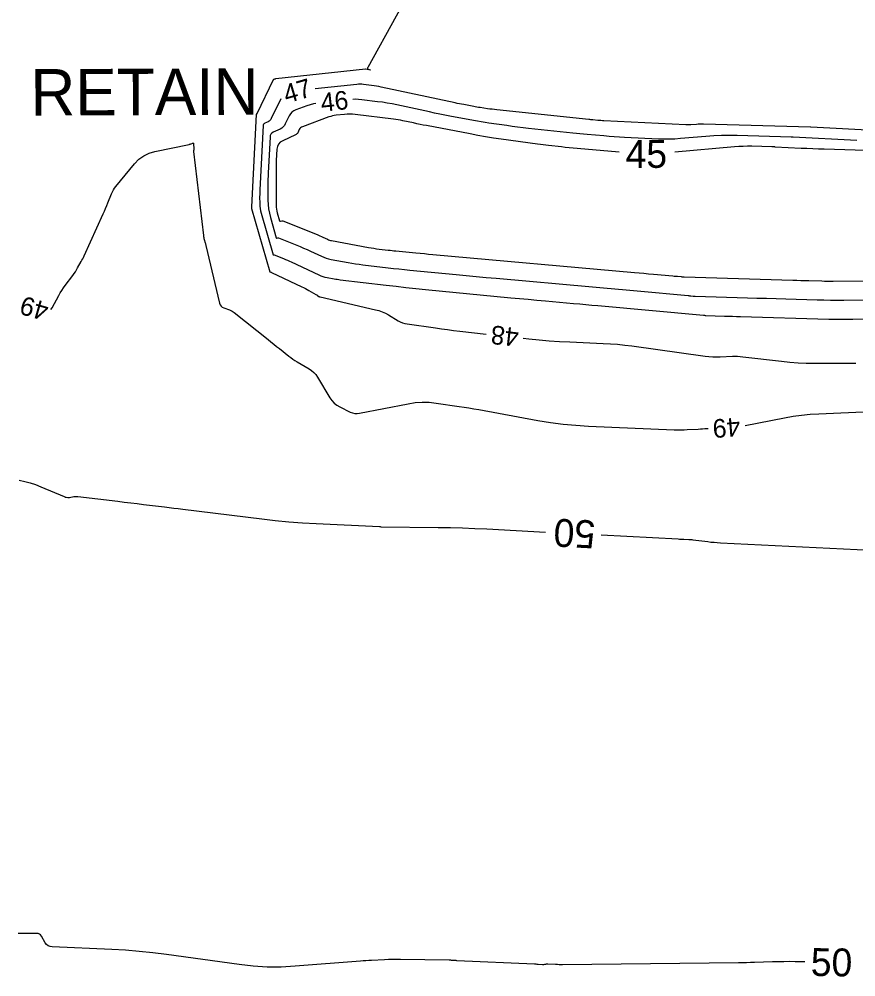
# Model space of a CAD drawing. Extents: x 2384780 to 2405861, y 547869 to 573706.
# Drawn here: x 2393194.6 to 2393284.5, y 552620 to 552723.1 of the extents above; entities that cross this region are included whole.
import ezdxf

# ---------------------------------------------------------------- set-up
doc = ezdxf.new("R2010")
doc.units = 0
for name, color, linetype in [('Breaklines', 7, 'Continuous'), ('Old_Level_60', 7, 'Continuous'), ('Old_Level_61', 7, 'Continuous')]:
    doc.layers.add(name, color=color, linetype=linetype)

msp = doc.modelspace()

# ---------------------------------------------------------------- linework, layer by layer
at = {"layer": 'Old_Level_60'}
for points in [[(2393238.1735, 552728.95825), (2393232.05975, 552717.871), (2393232.03925, 552717.81675), (2393232.0415, 552717.76975), (2393232.06625, 552717.7295), (2393232.11375, 552717.6965), (2393232.30575, 552717.59975), (2393232.33625, 552717.583), (2393232.345, 552717.5735), (2393232.33225, 552717.572), (2393232.298, 552717.57775), (2393231.8365, 552717.677), (2393231.833, 552717.67775), (2393231.82925, 552717.67825), (2393231.82575, 552717.67875), (2393231.822, 552717.67925), (2393231.81, 552717.68075), (2393231.8075, 552717.681), (2393231.80475, 552717.68125), (2393231.80225, 552717.681), (2393231.79975, 552717.681), (2393222.153, 552716.63275), (2393222.1245, 552716.62875), (2393222.09625, 552716.623), (2393222.06875, 552716.61575), (2393222.0415, 552716.60675), (2393221.953, 552716.57425), (2393221.93525, 552716.566), (2393221.92, 552716.55475), (2393221.9075, 552716.541), (2393221.8975, 552716.524), (2393220.1425, 552712.8735), (2393220.13625, 552712.863), (2393220.12875, 552712.854), (2393220.1195, 552712.8465), (2393220.109, 552712.8405), (2393220.07175, 552712.82325), (2393220.06475, 552712.819), (2393220.0595, 552712.8135), (2393220.05625, 552712.80675), (2393220.055, 552712.7985), (2393219.549, 552702.88225), (2393219.54825, 552702.86175), (2393219.5475, 552702.84125), (2393219.54725, 552702.82075), (2393219.54725, 552702.8), (2393219.5475, 552702.733), (2393219.548, 552702.7185), (2393219.5495, 552702.7045), (2393219.552, 552702.69025), (2393219.5555, 552702.6765), (2393221.52225, 552695.88275), (2393221.52275, 552695.88175), (2393221.5235, 552695.881), (2393221.5245, 552695.88075), (2393221.52575, 552695.88075), (2393221.53025, 552695.882), (2393221.53125, 552695.88225), (2393221.532, 552695.88225), (2393221.533, 552695.882), (2393221.534, 552695.88175), (2393221.62725, 552695.8445), (2393221.647, 552695.8365), (2393221.66675, 552695.828), (2393221.6865, 552695.81925), (2393221.706, 552695.81025), (2393224.972, 552694.274), (2393225.16225, 552694.18225), (2393225.35025, 552694.0865), (2393225.53625, 552693.987), (2393225.72025, 552693.8835), (2393226.48175, 552693.44475), (2393226.5275, 552693.4175), (2393226.5725, 552693.38925), (2393226.617, 552693.36), (2393226.66075, 552693.3295), (2393226.80225, 552693.2285), (2393226.83325, 552693.2085), (2393226.866, 552693.19175), (2393226.9, 552693.1785), (2393226.9355, 552693.1685)], [(2393294.628, 552710.66525), (2393279.71925, 552711.4425), (2393279.715, 552711.44275), (2393279.7105, 552711.443), (2393279.706, 552711.44325), (2393279.7015, 552711.44325), (2393279.687, 552711.44375), (2393279.684, 552711.44375), (2393279.681, 552711.444), (2393279.67775, 552711.444), (2393279.67475, 552711.44425), (2393268.15125, 552711.7675), (2393267.964, 552711.77), (2393267.77675, 552711.76725), (2393267.59, 552711.759), (2393267.40325, 552711.74525), (2393266.79325, 552711.69175), (2393266.6625, 552711.6825), (2393266.53175, 552711.67775), (2393266.40075, 552711.67775), (2393266.26975, 552711.682), (2393257.4505, 552712.1285), (2393257.28775, 552712.1375), (2393257.125, 552712.14825), (2393256.9625, 552712.16025), (2393256.8, 552712.174), (2393256.26925, 552712.2215), (2393256.15575, 552712.232), (2393256.042, 552712.24275), (2393255.9285, 552712.254), (2393255.815, 552712.26575), (2393245.93525, 552713.3075), (2393245.687, 552713.33475), (2393245.439, 552713.36425), (2393245.19125, 552713.39575), (2393244.94375, 552713.42925), (2393244.13575, 552713.54275), (2393243.96275, 552713.568), (2393243.79025, 552713.5955), (2393243.618, 552713.62525), (2393243.44625, 552713.65725), (2393242.37275, 552713.8635), (2393242.143, 552713.90825), (2393241.91325, 552713.9545), (2393241.684, 552714.00175), (2393241.45475, 552714.05025), (2393233.50675, 552715.7575), (2393233.2485, 552715.81), (2393232.9895, 552715.8565), (2393232.72925, 552715.89725), (2393232.46825, 552715.932), (2393231.614, 552716.0365), (2393231.43075, 552716.0535), (2393231.2475, 552716.06), (2393231.06425, 552716.056), (2393230.881, 552716.04125), (2393226.408, 552715.55525)], [(2393222.70025, 552714.48025), (2393221.6805, 552712.3595), (2393221.6185, 552712.25375), (2393221.54175, 552712.163), (2393221.44975, 552712.08775), (2393221.343, 552712.02775), (2393220.96975, 552711.85625), (2393220.89925, 552711.813), (2393220.8475, 552711.757), (2393220.81475, 552711.68825), (2393220.80075, 552711.60675), (2393220.448, 552704.6885), (2393220.44025, 552704.51375), (2393220.43475, 552704.33925), (2393220.432, 552704.1645), (2393220.43125, 552703.98975)], [(2393226.48025, 552714.00275), (2393226.21275, 552713.94875), (2393225.85, 552713.8525), (2393225.4925, 552713.734), (2393224.333, 552713.31075), (2393224.10125, 552713.2015), (2393223.90275, 552713.0555), (2393223.738, 552712.8725), (2393223.60675, 552712.6525), (2393223.19, 552711.786), (2393223.0885, 552711.61275), (2393222.9625, 552711.46425), (2393222.812, 552711.341), (2393222.637, 552711.2425), (2393221.88575, 552710.89725), (2393221.74375, 552710.8105), (2393221.63975, 552710.69775), (2393221.57375, 552710.5595), (2393221.54575, 552710.39525), (2393221.34725, 552706.507), (2393221.3325, 552706.17225), (2393221.32225, 552705.83725), (2393221.31675, 552705.50225), (2393221.3155, 552705.16725)], [(2393284.63775, 552710.01775), (2393277.792, 552710.37475), (2393277.7725, 552710.37575), (2393277.75275, 552710.3765), (2393277.73325, 552710.37725), (2393277.71375, 552710.378), (2393277.65, 552710.38), (2393277.63625, 552710.3805), (2393277.6225, 552710.38075), (2393277.60875, 552710.38125), (2393277.59525, 552710.3815), (2393271.7785, 552710.54475), (2393270.9375, 552710.55625), (2393270.0975, 552710.5435), (2393269.258, 552710.50625), (2393268.41925, 552710.445), (2393265.68075, 552710.20475), (2393265.09375, 552710.16325), (2393264.50625, 552710.14225), (2393263.9185, 552710.14175), (2393263.3305, 552710.16125), (2393259.66625, 552710.34675), (2393259.113, 552710.3775), (2393258.56025, 552710.4135), (2393258.00775, 552710.45475), (2393257.4555, 552710.5015), (2393255.65275, 552710.663), (2393255.2665, 552710.69825), (2393254.88025, 552710.73525), (2393254.49425, 552710.7735), (2393254.1085, 552710.8135), (2393249.35675, 552711.3145), (2393248.76675, 552711.37925), (2393248.177, 552711.44925), (2393247.58825, 552711.524), (2393246.99975, 552711.604), (2393245.079, 552711.8735), (2393244.66775, 552711.93375), (2393244.2575, 552711.99925), (2393243.848, 552712.07), (2393243.4395, 552712.14575), (2393240.88775, 552712.63625), (2393240.34125, 552712.74275), (2393239.79525, 552712.85225), (2393239.25, 552712.96475), (2393238.70525, 552713.08025), (2393235.17675, 552713.83825), (2393234.66425, 552713.94225), (2393234.14975, 552714.03475), (2393233.633, 552714.1155), (2393233.11475, 552714.18475), (2393231.41775, 552714.392), (2393231.054, 552714.426), (2393230.69025, 552714.43875), (2393230.45575, 552714.43375)], [(2393197.9695, 552691.81775), (2393198.10475, 552692), (2393198.82275, 552693.32125), (2393198.9815, 552693.60125), (2393199.1505, 552693.87475), (2393199.32925, 552694.14175), (2393199.51825, 552694.40225), (2393200.333, 552695.4845), (2393200.47475, 552695.6795), (2393200.60925, 552695.879), (2393200.73675, 552696.08325), (2393200.85725, 552696.292), (2393201.23925, 552696.981), (2393201.31975, 552697.1295), (2393201.39725, 552697.2795), (2393201.47175, 552697.43075), (2393201.54325, 552697.58375), (2393203.60525, 552702.1035), (2393203.73825, 552702.4), (2393203.86775, 552702.698), (2393203.99375, 552702.99775), (2393204.11575, 552703.299), (2393204.50925, 552704.28525), (2393204.601, 552704.49225), (2393204.708, 552704.69025), (2393204.83, 552704.87925), (2393204.967, 552705.0595), (2393206.97925, 552707.506), (2393207.43975, 552707.98175), (2393207.9585, 552708.36075), (2393208.53575, 552708.64275), (2393209.1715, 552708.828), (2393212.84625, 552709.5835), (2393212.9025, 552709.59675), (2393212.9575, 552709.613), (2393213.0115, 552709.63225), (2393213.0645, 552709.65475), (2393213.236, 552709.733), (2393213.2685, 552709.7425), (2393213.292, 552709.738), (2393213.30675, 552709.719), (2393213.31275, 552709.68575), (2393213.33575, 552709.0925), (2393213.33625, 552709.06625), (2393213.3365, 552709.04), (2393213.33575, 552709.0135), (2393213.33425, 552708.98725), (2393213.32875, 552708.90125), (2393213.328, 552708.883), (2393213.32825, 552708.8645), (2393213.329, 552708.84625), (2393213.33075, 552708.82775), (2393214.38525, 552699.7715), (2393214.40025, 552699.6645), (2393214.41975, 552699.5585), (2393214.444, 552699.45325), (2393214.47275, 552699.34925), (2393214.5745, 552699.0105), (2393214.59575, 552698.93775), (2393214.616, 552698.86475), (2393214.635, 552698.7915), (2393214.653, 552698.71775), (2393216.11275, 552692.519), (2393216.17675, 552692.33925), (2393216.27675, 552692.19175), (2393216.4125, 552692.07625), (2393216.5845, 552691.99325), (2393217.20425, 552691.77425), (2393217.33425, 552691.72225), (2393217.4585, 552691.66), (2393217.577, 552691.5875), (2393217.69, 552691.50475), (2393221.3405, 552688.591), (2393221.64675, 552688.34625), (2393221.95275, 552688.10125), (2393222.2585, 552687.85575), (2393222.56375, 552687.61), (2393223.561, 552686.8065), (2393223.7775, 552686.6385), (2393224, 552686.479), (2393224.228, 552686.3275), (2393224.46175, 552686.1845), (2393225.75125, 552685.42725), (2393226.01375, 552685.25075), (2393226.2485, 552685.0465), (2393226.45575, 552684.81425), (2393226.635, 552684.55375), (2393227.9805, 552682.324), (2393228.1955, 552682.01725), (2393228.447, 552681.7505), (2393228.735, 552681.52325), (2393229.05925, 552681.33575), (2393230.178, 552680.7885), (2393230.4205, 552680.69225), (2393230.6685, 552680.63825), (2393230.922, 552680.6265), (2393231.181, 552680.657), (2393236.38975, 552681.6815), (2393237.1415, 552681.797), (2393237.895, 552681.8485), (2393238.65, 552681.8355)], [(2393221.3155, 552705.16725), (2393221.32125, 552703.603), (2393221.3395, 552703.1265), (2393221.3905, 552702.655), (2393221.47425, 552702.188), (2393221.591, 552701.7255), (2393222.22225, 552699.545), (2393222.23275, 552699.52175), (2393222.24825, 552699.50725), (2393222.2685, 552699.50175), (2393222.29375, 552699.50475), (2393222.38475, 552699.5295), (2393222.404, 552699.533), (2393222.42325, 552699.5335), (2393222.44225, 552699.531), (2393222.461, 552699.525), (2393224.427, 552698.73875), (2393224.7955, 552698.58825), (2393225.1615, 552698.43225), (2393225.52525, 552698.271), (2393225.88675, 552698.10425), (2393227.06375, 552697.55075), (2393227.3185, 552697.44075), (2393227.579, 552697.3475), (2393227.845, 552697.27175), (2393228.11625, 552697.21275), (2393229.9535, 552696.8755), (2393230.34775, 552696.8065), (2393230.74275, 552696.74375), (2393231.139, 552696.68725), (2393231.536, 552696.63725), (2393234.248, 552696.31825), (2393234.82925, 552696.25125), (2393235.41075, 552696.18725), (2393235.99275, 552696.126), (2393236.575, 552696.06775), (2393241.57575, 552695.58), (2393242.6475, 552695.4765), (2393243.7195, 552695.37525), (2393244.7915, 552695.276), (2393245.86375, 552695.17925), (2393256.21775, 552694.25475), (2393257.4235, 552694.147), (2393258.629, 552694.0385), (2393259.8345, 552693.92925), (2393261.04, 552693.81975), (2393266.518, 552693.32025), (2393266.59175, 552693.3135), (2393266.6655, 552693.307), (2393266.73925, 552693.30025), (2393266.813, 552693.29375), (2393267.05375, 552693.27225), (2393267.10525, 552693.268), (2393267.157, 552693.2645), (2393267.20875, 552693.26175), (2393267.2605, 552693.25975), (2393272.8845, 552693.08825), (2393273.915, 552693.057), (2393274.94575, 552693.026), (2393275.97625, 552692.99525), (2393277.007, 552692.96475), (2393280.37375, 552692.866), (2393281.095, 552692.848), (2393281.81675, 552692.836), (2393282.53825, 552692.83025), (2393283.26, 552692.83075), (2393287.00075, 552692.84875)], [(2393220.43125, 552703.98975), (2393220.43425, 552703.17425), (2393220.44375, 552702.92575), (2393220.47025, 552702.67975), (2393220.514, 552702.43625), (2393220.575, 552702.195), (2393221.87225, 552697.714), (2393221.87775, 552697.70175), (2393221.88575, 552697.69425), (2393221.8965, 552697.69125), (2393221.90975, 552697.69275), (2393221.9575, 552697.70575), (2393221.96775, 552697.70775), (2393221.97775, 552697.708), (2393221.98775, 552697.7065), (2393221.9975, 552697.7035), (2393222.991, 552697.306), (2393223.20325, 552697.2195), (2393223.414, 552697.12975), (2393223.6235, 552697.03675), (2393223.8315, 552696.94075), (2393226.78675, 552695.55075), (2393227.0035, 552695.45725), (2393227.22475, 552695.378), (2393227.45075, 552695.3135), (2393227.6815, 552695.2635), (2393228.44275, 552695.12375), (2393228.606, 552695.09525), (2393228.76975, 552695.06925), (2393228.93375, 552695.04575), (2393229.09825, 552695.025), (2393234.0375, 552694.444), (2393235.096, 552694.322), (2393236.15525, 552694.2055), (2393237.215, 552694.094), (2393238.2755, 552693.988), (2393247.4365, 552693.094), (2393248.36625, 552693.00425), (2393249.296, 552692.9165), (2393250.22625, 552692.8305), (2393251.1565, 552692.7465), (2393254.1955, 552692.47525), (2393254.84675, 552692.41675), (2393255.498, 552692.35825), (2393256.149, 552692.29925), (2393256.80025, 552692.24), (2393268.154, 552691.205), (2393268.18125, 552691.2025), (2393268.2085, 552691.2), (2393268.236, 552691.1975), (2393268.26325, 552691.195), (2393268.3525, 552691.187), (2393268.3715, 552691.1855), (2393268.39075, 552691.18425), (2393268.40975, 552691.18325), (2393268.429, 552691.1825), (2393270.422, 552691.12175), (2393270.84925, 552691.10875), (2393271.27625, 552691.096), (2393271.70325, 552691.08325), (2393272.1305, 552691.0705), (2393281.6255, 552690.792), (2393281.8845, 552690.7855), (2393282.1435, 552690.78125), (2393282.40275, 552690.77925), (2393282.662, 552690.77925), (2393283.5085, 552690.7835), (2393283.69, 552690.78475), (2393283.8715, 552690.78675), (2393284.05275, 552690.7895), (2393284.23425, 552690.793), (2393297.52775, 552691.08425)], [(2393226.9355, 552693.1685), (2393232.89875, 552691.795), (2393233.25875, 552691.6975), (2393233.60775, 552691.573), (2393233.94625, 552691.4215), (2393234.27375, 552691.243), (2393235.32575, 552690.616), (2393235.5555, 552690.49375), (2393235.794, 552690.39575), (2393236.04075, 552690.322), (2393236.29625, 552690.2725), (2393239.33325, 552689.8345), (2393239.98425, 552689.74325), (2393240.636, 552689.65725), (2393241.2885, 552689.57675), (2393241.9415, 552689.5015), (2393244.789, 552689.1845)], [(2393248.7645, 552688.74225), (2393249.38075, 552688.67375), (2393250.47925, 552688.561), (2393251.579, 552688.46675), (2393252.68, 552688.391), (2393253.78275, 552688.334), (2393257.387, 552688.178), (2393258.1585, 552688.1355), (2393258.92825, 552688.07525), (2393259.6965, 552687.99675), (2393260.46325, 552687.9005), (2393268.35325, 552686.81575), (2393268.753, 552686.76975), (2393269.1535, 552686.7415), (2393269.555, 552686.73075), (2393269.95725, 552686.73775), (2393271.2725, 552686.78975), (2393271.55425, 552686.79525), (2393271.8355, 552686.7895), (2393272.11625, 552686.77275), (2393272.3965, 552686.74475), (2393276.54575, 552686.247), (2393277.4355, 552686.15375), (2393278.327, 552686.087), (2393279.22025, 552686.047), (2393280.115, 552686.0335), (2393283.2175, 552686.03325), (2393283.8825, 552686.03675), (2393284.547, 552686.04725)], [(2393238.65, 552681.8355), (2393239.40675, 552681.7585), (2393241.8815, 552681.4015), (2393242.41125, 552681.3225), (2393242.94025, 552681.2385), (2393243.4685, 552681.1495), (2393243.996, 552681.0555), (2393250.3355, 552679.8935), (2393251.69675, 552679.668), (2393253.06325, 552679.49), (2393254.435, 552679.35925), (2393255.81225, 552679.276), (2393265.005, 552678.878), (2393265.359, 552678.86725), (2393265.71275, 552678.86575), (2393266.0665, 552678.8735), (2393266.42025, 552678.89075), (2393267.57525, 552678.96175), (2393267.823, 552678.97625), (2393268.0705, 552678.9895), (2393268.31825, 552679.00125), (2393268.566, 552679.012), (2393268.648, 552679.01525)], [(2393272.631, 552679.32575), (2393276.86925, 552680.1665), (2393277.78825, 552680.3305), (2393278.71175, 552680.459), (2393279.63925, 552680.55175), (2393280.57125, 552680.609), (2393286.1155, 552680.8425)]]:
    msp.add_lwpolyline(points, dxfattribs=at)
at = {"layer": 'Old_Level_61'}
for points in [[(2393259.08675, 552708.74175), (2393254.56075, 552709.147), (2393254.1395, 552709.1855), (2393253.71825, 552709.22575), (2393253.2975, 552709.2675), (2393252.8765, 552709.311), (2393251.50225, 552709.456), (2393251.208, 552709.48825), (2393250.914, 552709.52325), (2393250.62025, 552709.5605), (2393250.32675, 552709.6005), (2393246.4035, 552710.15075), (2393245.56375, 552710.274), (2393244.72575, 552710.40775), (2393243.88925, 552710.55225), (2393243.05475, 552710.707), (2393238.3865, 552711.60425), (2393238.031, 552711.6735), (2393237.67625, 552711.74475), (2393237.3215, 552711.818), (2393236.9675, 552711.893), (2393235.81125, 552712.14125), (2393235.563, 552712.19175), (2393235.31375, 552712.2365), (2393235.0635, 552712.27575), (2393234.8125, 552712.30925), (2393230.696, 552712.81175), (2393230.4145, 552712.838), (2393230.13325, 552712.848), (2393229.85175, 552712.84175), (2393229.57025, 552712.81925), (2393228.65025, 552712.71925), (2393228.45425, 552712.692), (2393228.26125, 552712.65325), (2393228.071, 552712.60275), (2393227.88325, 552712.5405), (2393225.02075, 552711.4955), (2393224.91625, 552711.44625), (2393224.82675, 552711.38025), (2393224.75225, 552711.29775), (2393224.693, 552711.1985), (2393224.524, 552710.847), (2393224.48275, 552710.77675), (2393224.43175, 552710.7165), (2393224.37075, 552710.6665), (2393224.29975, 552710.6265), (2393222.91225, 552709.989), (2393222.65, 552709.82875), (2393222.458, 552709.62075), (2393222.336, 552709.36525), (2393222.28425, 552709.0625), (2393222.2225, 552707.85375), (2393222.21125, 552707.5945), (2393222.20325, 552707.3355), (2393222.199, 552707.07625), (2393222.198, 552706.817)], [(2393302.1405, 552708.40875), (2393281.1455, 552709.05775), (2393280.52775, 552709.0785), (2393279.91025, 552709.1025), (2393279.29275, 552709.12975), (2393278.6755, 552709.16025), (2393275.8645, 552709.307), (2393275.83, 552709.30875), (2393275.79525, 552709.31025), (2393275.76075, 552709.3115), (2393275.726, 552709.31275), (2393275.61275, 552709.31625), (2393275.5885, 552709.317), (2393275.56425, 552709.31775), (2393275.54, 552709.31825), (2393275.51575, 552709.319), (2393273.3455, 552709.38), (2393272.88075, 552709.38625), (2393272.41625, 552709.37925), (2393271.95225, 552709.35875), (2393271.4885, 552709.32475), (2393265.0725, 552708.76175)], [(2393222.198, 552706.817), (2393222.21175, 552703.02875), (2393222.2195, 552702.8235), (2393222.2415, 552702.62025), (2393222.27775, 552702.419), (2393222.328, 552702.21975), (2393222.57225, 552701.37625), (2393222.58775, 552701.342), (2393222.6105, 552701.3205), (2393222.6405, 552701.31225), (2393222.678, 552701.31675), (2393222.812, 552701.35325), (2393222.8405, 552701.3585), (2393222.86875, 552701.35925), (2393222.897, 552701.35525), (2393222.92475, 552701.3465), (2393226.6065, 552699.87425), (2393226.76075, 552699.81125), (2393226.914, 552699.746), (2393227.066, 552699.6785), (2393227.21725, 552699.60875), (2393227.70975, 552699.377), (2393227.81625, 552699.331), (2393227.92525, 552699.29225), (2393228.0365, 552699.2605), (2393228.15, 552699.23575), (2393232.1325, 552698.5045), (2393232.423, 552698.4535), (2393232.71425, 552698.40725), (2393233.00625, 552698.36575), (2393233.299, 552698.329), (2393234.256, 552698.2165), (2393234.46125, 552698.19275), (2393234.6665, 552698.17025), (2393234.872, 552698.1485), (2393235.0775, 552698.128), (2393237.22275, 552697.91875), (2393237.6825, 552697.87425), (2393238.1425, 552697.83075), (2393238.6025, 552697.78825), (2393239.0625, 552697.74675), (2393260.7515, 552695.81025), (2393261.256, 552695.76525), (2393261.76025, 552695.71975), (2393262.2645, 552695.67425), (2393262.769, 552695.62825), (2393264.882, 552695.43575), (2393265.00225, 552695.42475), (2393265.12225, 552695.41375), (2393265.2425, 552695.403), (2393265.3625, 552695.39225), (2393265.755, 552695.35725), (2393265.839, 552695.35025), (2393265.92325, 552695.34475), (2393266.0075, 552695.34025), (2393266.092, 552695.337), (2393277.75275, 552694.98125), (2393278.18375, 552694.96825), (2393278.615, 552694.95525), (2393279.04625, 552694.9425), (2393279.47725, 552694.92975), (2393280.88575, 552694.8885), (2393281.18775, 552694.88075), (2393281.4895, 552694.876), (2393281.7915, 552694.8735), (2393282.09325, 552694.87375), (2393292.23, 552694.92275)], [(2393194.5665, 552673.45), (2393195.1635, 552673.324), (2393195.751, 552673.16575), (2393196.329, 552672.9755), (2393196.897, 552672.75275), (2393199.424, 552671.68225), (2393199.4755, 552671.662), (2393199.528, 552671.645), (2393199.5815, 552671.63125), (2393199.63575, 552671.62025), (2393199.81475, 552671.59), (2393199.853, 552671.58525), (2393199.89125, 552671.584), (2393199.9295, 552671.58625), (2393199.96775, 552671.59175), (2393200.461, 552671.68675), (2393200.56675, 552671.70275), (2393200.67275, 552671.71075), (2393200.77925, 552671.71025), (2393200.886, 552671.7015), (2393205.1725, 552671.1805), (2393205.866, 552671.0965), (2393206.5595, 552671.0125), (2393207.253, 552670.92875), (2393207.94675, 552670.845), (2393210.21225, 552670.572), (2393210.69775, 552670.5135), (2393211.18325, 552670.45475), (2393211.66875, 552670.3955), (2393212.15425, 552670.336), (2393220.65075, 552669.29425), (2393222.11075, 552669.12875), (2393223.573, 552668.99025), (2393225.03775, 552668.8785), (2393226.5045, 552668.79375), (2393233.31625, 552668.463), (2393233.336, 552668.462), (2393233.3555, 552668.46075), (2393233.37525, 552668.45925), (2393233.395, 552668.45775), (2393233.45925, 552668.452), (2393233.47325, 552668.45075), (2393233.487, 552668.45), (2393233.50075, 552668.44925), (2393233.5145, 552668.449), (2393239.63325, 552668.3725), (2393240.94425, 552668.3495), (2393242.25475, 552668.31375), (2393243.56475, 552668.265), (2393244.8745, 552668.20325), (2393251.158, 552667.87575)], [(2393257.15, 552667.56375), (2393265.432, 552667.13225), (2393265.589, 552667.1245), (2393265.746, 552667.1175), (2393265.903, 552667.11125), (2393266.06, 552667.10575), (2393266.573, 552667.089), (2393266.683, 552667.08425), (2393266.7925, 552667.0765), (2393266.902, 552667.06625), (2393267.01125, 552667.05325), (2393268.613, 552666.843), (2393268.9565, 552666.8015), (2393269.30075, 552666.767), (2393269.6455, 552666.7395), (2393269.991, 552666.719), (2393296.4475, 552665.4185)], [(2393279.06775, 552621.6225), (2393278.0095, 552621.639), (2393277.40675, 552621.645), (2393276.804, 552621.64325), (2393276.2015, 552621.6345), (2393275.599, 552621.61825), (2393273.631, 552621.55325), (2393273.20925, 552621.5405), (2393272.7875, 552621.53), (2393272.36575, 552621.522), (2393271.94375, 552621.5165), (2393252.9965, 552621.31775), (2393252.8125, 552621.31725), (2393252.62825, 552621.32), (2393252.44425, 552621.32575), (2393252.26025, 552621.33475), (2393251.437, 552621.382), (2393251.4195, 552621.38275), (2393251.40175, 552621.38275), (2393251.384, 552621.382), (2393251.36625, 552621.38075), (2393251.3085, 552621.37525), (2393251.29625, 552621.37375), (2393251.284, 552621.372), (2393251.27175, 552621.36975), (2393251.2595, 552621.36725), (2393251.155, 552621.34275), (2393251.1325, 552621.33775), (2393251.11, 552621.33375), (2393251.08725, 552621.3305), (2393251.06425, 552621.32775), (2393250.93925, 552621.316), (2393250.9125, 552621.314), (2393250.88575, 552621.31325), (2393250.859, 552621.3135), (2393250.832, 552621.315), (2393250.3785, 552621.34875), (2393250.28125, 552621.3555), (2393250.184, 552621.36175), (2393250.08675, 552621.36725), (2393249.9895, 552621.372), (2393241.65175, 552621.74875), (2393241.56975, 552621.75275), (2393241.488, 552621.757), (2393241.40625, 552621.76175), (2393241.32425, 552621.76675), (2393241.057, 552621.784), (2393240.99975, 552621.7875), (2393240.9425, 552621.79025), (2393240.88525, 552621.79225), (2393240.82775, 552621.7935), (2393235.5725, 552621.88), (2393235.1445, 552621.8835), (2393234.71675, 552621.8795), (2393234.289, 552621.86825), (2393233.86125, 552621.84975), (2393232.46475, 552621.7775), (2393232.1655, 552621.761), (2393231.8665, 552621.7425), (2393231.56775, 552621.72175), (2393231.26875, 552621.69925), (2393224.24175, 552621.143), (2393222.73725, 552621.06475), (2393221.23525, 552621.0685), (2393219.7355, 552621.154), (2393218.23825, 552621.32175), (2393210.419, 552622.41175), (2393208.951, 552622.59875), (2393207.48, 552622.7505), (2393206.00575, 552622.867), (2393204.52825, 552622.94875), (2393198.12425, 552623.226), (2393197.89075, 552623.26225), (2393197.688, 552623.35), (2393197.5165, 552623.48875), (2393197.37575, 552623.679), (2393196.96675, 552624.3835), (2393196.86825, 552624.5155), (2393196.748, 552624.61), (2393196.606, 552624.6665), (2393196.44225, 552624.6855), (2393195.37825, 552624.68625), (2393195.15025, 552624.68675), (2393194.92225, 552624.6875), (2393194.69425, 552624.6885), (2393194.46625, 552624.69)]]:
    msp.add_lwpolyline(points, dxfattribs=at)

# ---------------------------------------------------------------- texts
at = {"layer": 'Breaklines'}
msp.add_text('RETAIN', height=5, rotation=0.2229861, dxfattribs=at).set_placement((2393195.787, 552712.6855))
at = {"layer": 'Old_Level_60'}
for s, rotation, p in [('47', 16.1680611, (2393223.3225, 552713.97575)), ('46', 6.1872028, (2393227.102, 552713.08525)), ('49', 164.0917472, (2393197.88925, 552692.4895)), ('48', 173.6521722, (2393248.38175, 552689.791)), ('49', 184.4588806, (2393272.0445, 552680.207))]:
    msp.add_text(s, height=2, rotation=rotation, dxfattribs=at).set_placement(p)
at = {"layer": 'Old_Level_61'}
for s, rotation, p in [('45', 0.1917333, (2393259.78275, 552707.05325)), ('50', 177.0179389, (2393256.59075, 552669.09475)), ('50', 359.0989667, (2393279.68225, 552620.1125))]:
    msp.add_text(s, height=3, rotation=rotation, dxfattribs=at).set_placement(p)

doc.saveas('drawing.dxf')
